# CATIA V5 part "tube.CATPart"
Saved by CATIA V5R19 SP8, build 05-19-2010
Part number: tube
Material "Cuivre": density 8900 kg/m3, Young's modulus 1.1e+11 Pa, Poisson ratio 0.33, thermal expansion 1.65e-05 1/K
Bounding box of the stored display mesh (mm): x -20 to 20, y -12.25 to 11.75, z -14.807 to 8.828
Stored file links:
  G:\EU_thinkMotion\CFAO_2010\MMS_groupe3\MMS_groupe3\A reprendre\ftixier\florent-tixier\florent-tixier\tube.CATPart
  C:\Users\Azote\Desktop\CFAO\coupe_tube1.CATProduct
  C:\Program Files\Dassault Systemes\B19\intel_a\startup\materials\French\Catalog.CATMaterial
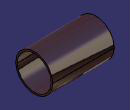
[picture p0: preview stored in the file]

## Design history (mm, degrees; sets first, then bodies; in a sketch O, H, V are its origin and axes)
Parameters
  epaisseur = 1 mm
External parameters (linked from other documents)
  External.Rt = 12 mm
Set1
  Sketch1 "tube", origin (0, 1.125, 13.9547), H (0, 1, 0), V (0, 0, 1), geometry linked from another document
  Point1 "centre_tube": linked copy from another document
Body1 (main body), material "Cuivre"
  Sketch2 on yz-plane, origin (0, 0, 0), H (0, 1, 0), V (0, 0, 1)
    projected circle E1 centre (-0.25, -2.9896) radius 12 from Sketch1
    circle A1 centre (-0.25, -2.9896) radius 11
    reference projected point E2 (-0.25, -2.9896) from Point1
    radius A1 = 11 {= External.Rt -epaisseur}
    concentricity: A1 E2
  Pad1: profile Sketch2, direction (1, 0, 0), length 20, mirrored extent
